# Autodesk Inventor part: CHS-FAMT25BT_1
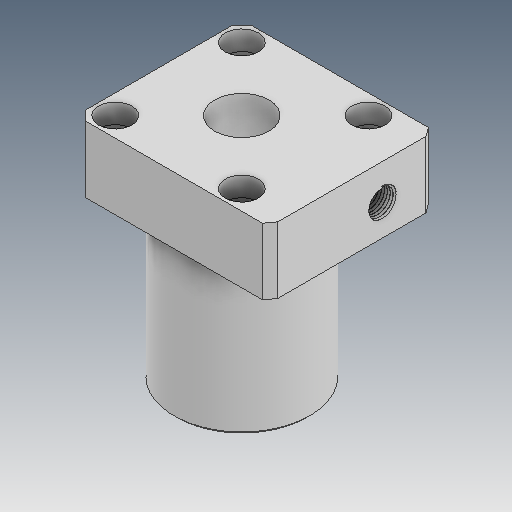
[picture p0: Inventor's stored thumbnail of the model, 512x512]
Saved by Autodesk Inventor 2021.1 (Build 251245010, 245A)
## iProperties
Created: 2019-05
Part Number: CHS-FAMT25BT_1
Material: Ogólny
Document SubType Name: Modeling
Designer: user
Density: 1 g/cm^3
Appearance: Domyślna
Author: user
Revision Number: ÈÎºÎ
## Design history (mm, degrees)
feature "ÊäÈë1"
node "Bryła1"
